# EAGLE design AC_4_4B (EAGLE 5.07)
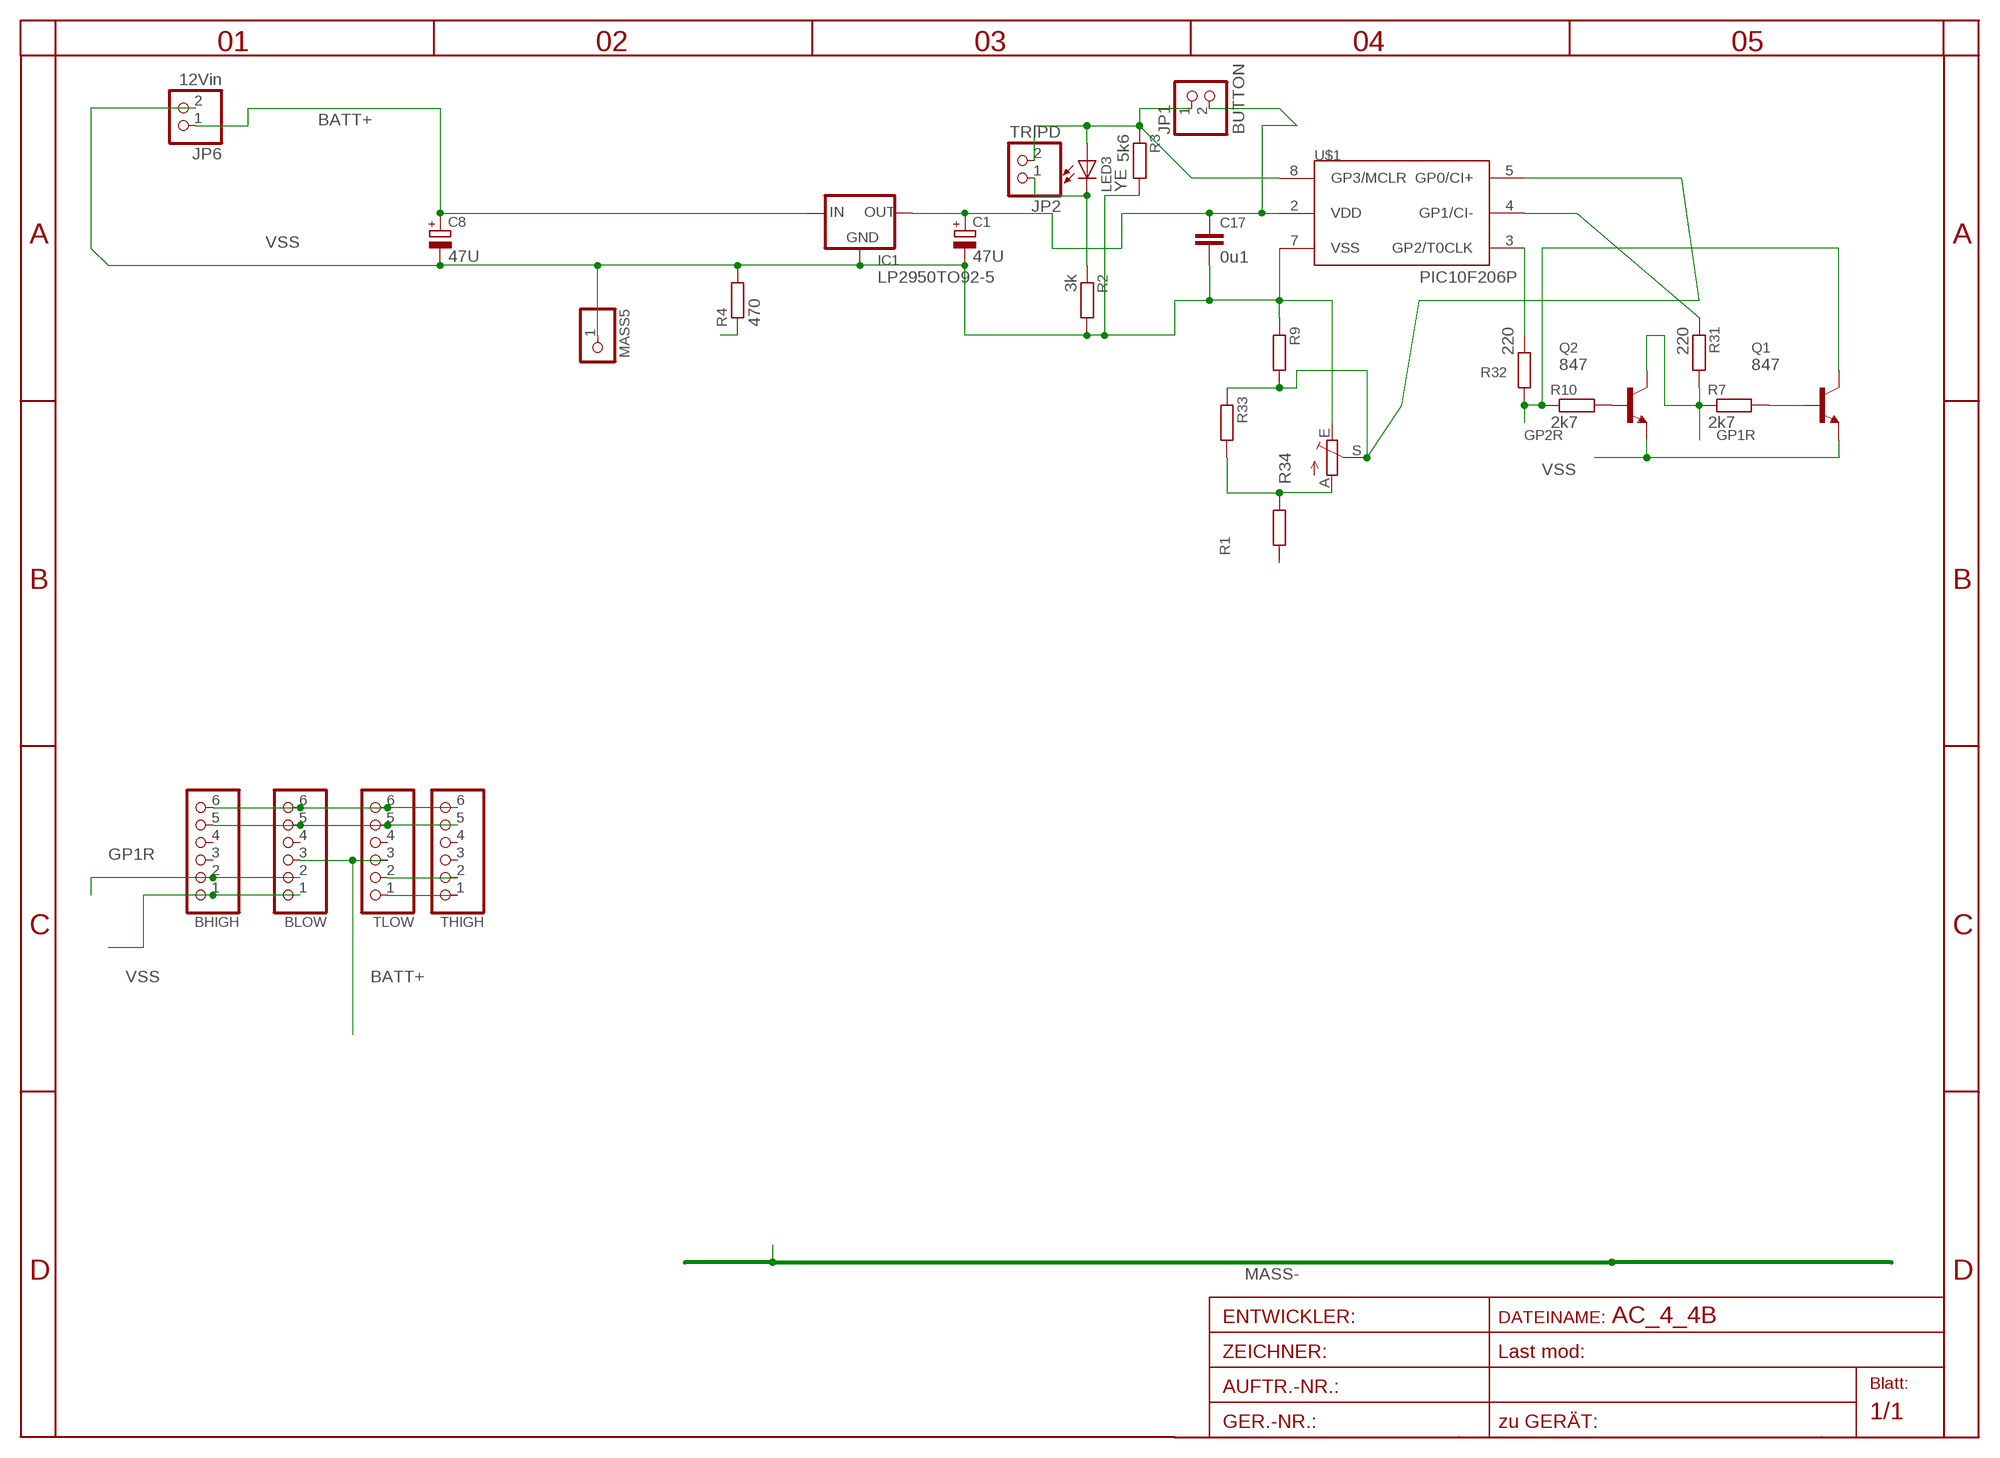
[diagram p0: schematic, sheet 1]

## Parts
BHIGH  PINHD-1X6  [1X06BOX]
BLOW  PINHD-1X6  [1X06BOX]
C1  47U  CPOL-EUE5-6  [E5-6]
C8  47U  CPOL-EUE5-5  [E5-5]
C17  0u1  C-EUC1206  [C1206]
IC1  LP2950TO92-5  [T092-5]
JP1  BUTTON  PINHD-1X2/90  [1X02/90]
JP2  TRIPD  PINHD-1X2/90  [1X02/90]
JP6  12Vin  PINHD-1X2STR  [1X02]
LED3  YE  LEDCHIPLED_1206  [CHIPLED_1206]
MASS5  PINHD-1X11MM6  [1X1MM8]
Q1  847  BC847ALT1SMD  [SOT23]
Q2  847  BC847ALT1SMD  [SOT23]
R1  R-EU_0207/35  [0207/35]
R2  3k  R-EU_R0805  [R0805]
R3  5k6  R-EU_R0805  [R0805]
R4  470  R-EU_0204/5  [0204/5]
R7  2k7  R-EU_R0805  [R0805]
R9  R-EU_R0805  [R0805]
R10  2k7  R-EU_R0805  [R0805]
R31  220  R-EU_R1206  [R1206]
R32  220  R-EU_R1206  [R1206]
R33  R-EU_R0805  [R0805]
R34  TRIM_EU-S64W  [S64W]
THIGH  PINHD-1X6  [1X06BOX]
TLOW  PINHD-1X6  [1X06BOX]
U$1  PIC10F206P  [DIL8]

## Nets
BATT+: BLOW.3 C8.+ IC1.3(IN) JP6.1 TLOW.3
GP1R: BHIGH.2 BLOW.2 Q2.3(C) R7.1 R31.2
GP2R: Q1.3(C) R10.1 R32.2 THIGH.2 TLOW.2
GP3: BHIGH.6 BLOW.6 JP1.1 JP2.2 LED3.A R3.1 THIGH.6 TLOW.6 U$1.8(GP3/MCLR)
N$1: R9.2 R33.1 R34.S U$1.5(GP0/CI+)
N$4: Q2.1(B) R10.2
N$7: Q1.1(B) R7.2
N$15: JP2.1 LED3.C R2.1
N$34: R4.1
N$39: R31.1 U$1.4(GP1/CI-)
N$42: R1.1 R33.2 R34.A
N$43: R32.1 U$1.3(GP2/T0CLK)
VDD: BHIGH.5 BLOW.5 C1.+ C17.1 IC1.1(OUT) JP1.2 THIGH.5 TLOW.5 U$1.2(VDD)
VSS: BHIGH.1 BLOW.1 C1.- C8.- C17.2 IC1.2(GND) JP6.2 MASS5.1 Q1.2(E) Q2.2(E) R2.2 R3.2 R4.2 R9.1 R34.E THIGH.1 TLOW.1 U$1.7(VSS)
Unconnected: BHIGH.3 BHIGH.4 BLOW.4 R1.2 THIGH.3 THIGH.4 TLOW.4

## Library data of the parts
BHIGH BLOW THIGH TLOW = pinhead:PINHD-1X6: PIN HEADER
C1 C8 = rcl-2:CPOL-EU: POLARIZED CAPACITOR, European symbol
C17 = rcl-2:C-EU: CAPACITOR, European symbol
IC1 = v-reg:LP2950?*: Source: http://cache.national.com/ds/LP/LP2950.pdf
JP1 JP2 JP6 = pinhead:PINHD-1X2: PIN HEADER
LED3 = led:LED: LED
MASS5 = pinhead:PINHD-1X1: PIN HEADER
Q1 Q2 = transistor-npn:BC847*: NPN Transistor
R1-R4 R7 R9 R10 R31-R33 = rcl-2:R-EU_: RESISTOR, European symbol
R34 = pot:TRIM_EU-: POTENTIOMETER
U$1 = microchip-5:PIC10F2*: uPC nW 0,25/0,5k Program Flash memory Comparator

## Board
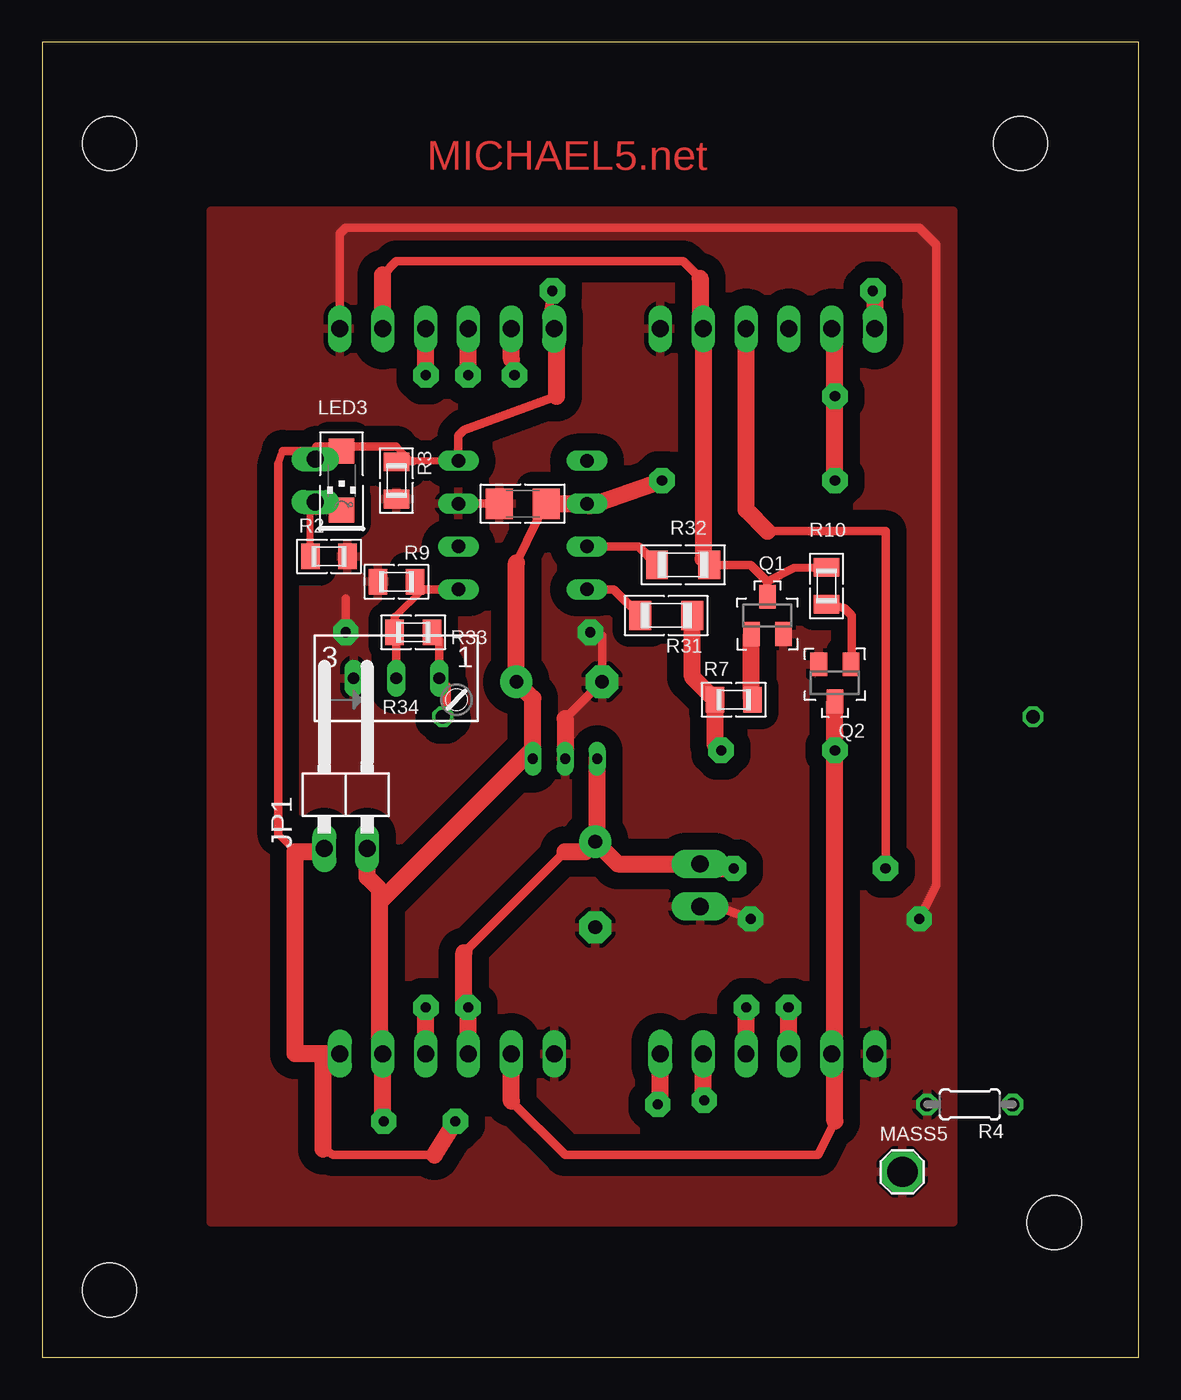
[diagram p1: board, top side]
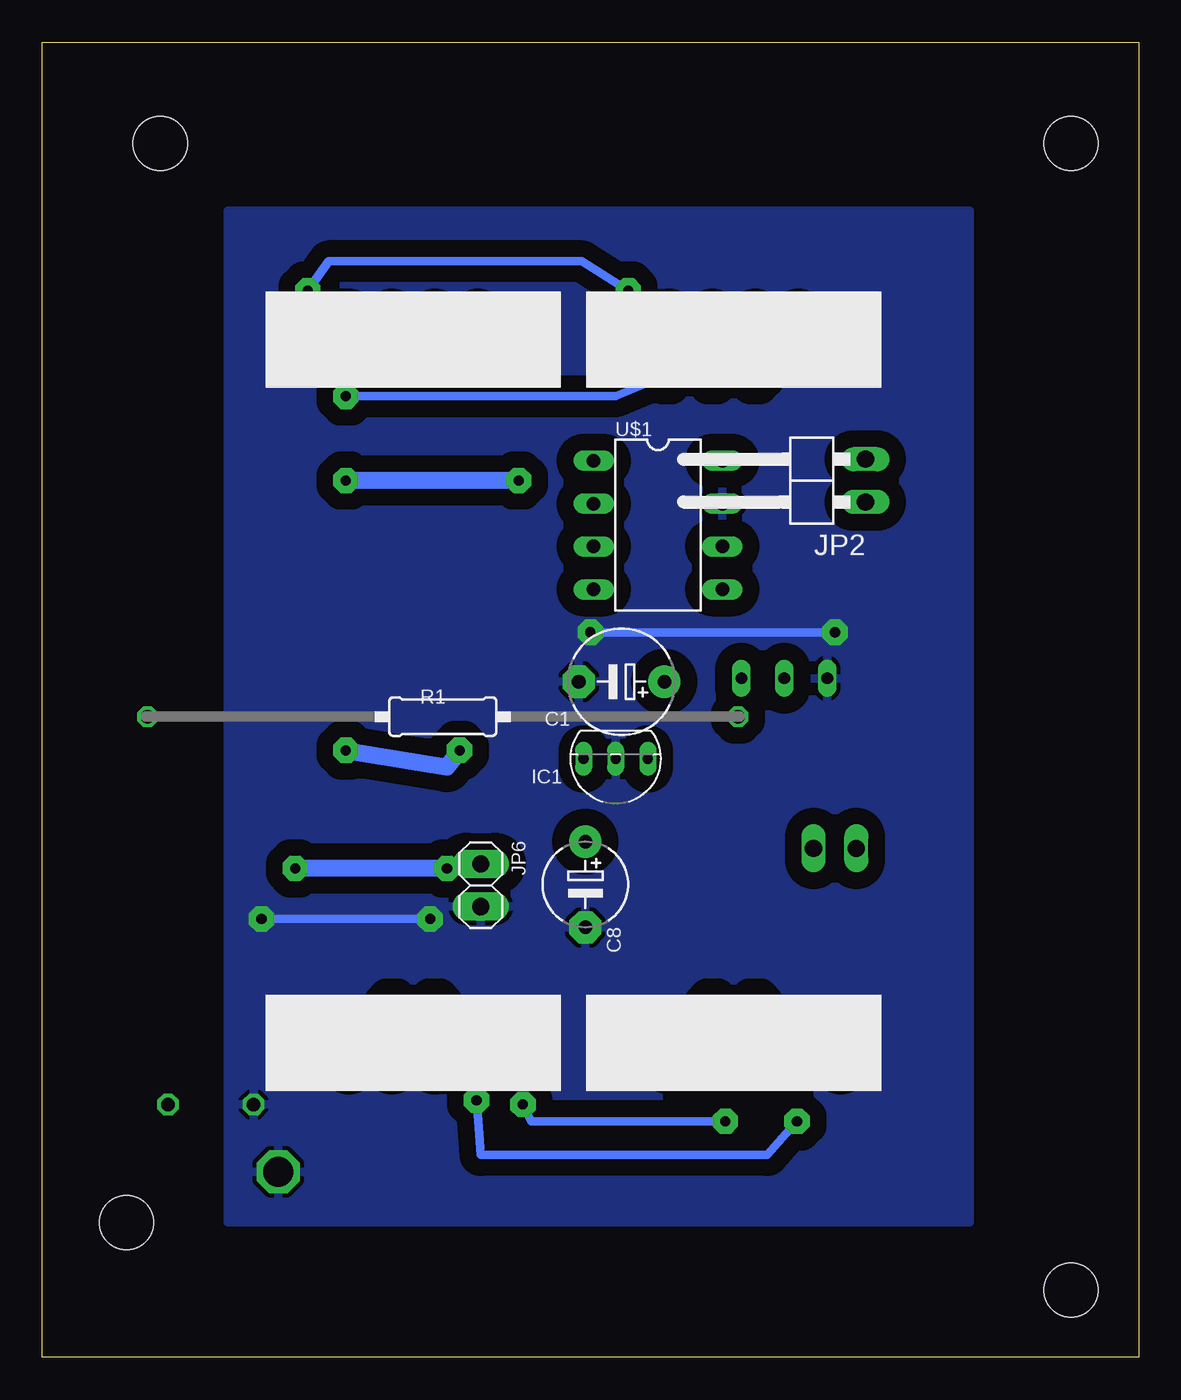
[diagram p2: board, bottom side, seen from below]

Size 65 x 78 mm. Coordinates in mm from the lower left corner, seen from the top.
Outline: 0,0 65,0 65,78 0,78 0,0
Copper layers (1*16): Top 0.035mm / dielectric 1.5mm / Bottom 0.035mm
Design rules "default *": minimum track width 12mil, minimum drill 24mil, track to track 8mil, track to pad 8mil, pad to pad 8mil, via to via 8mil, smd to smd 8mil, copper to edge 40mil, drill to drill 8mil, minimum pad ring 8mil, minimum via ring 8mil, stop-mask expansion 4mil, vias tented up to drill 0mil, thermal gap 10mil
Holes 3.2 mm at 4,72 4,4 58,72 60,8

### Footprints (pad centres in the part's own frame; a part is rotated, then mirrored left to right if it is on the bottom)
1X06BOX = drill 1 long: 1 -6.35,0; 2 -3.81,0; 3 -1.27,0; 4 1.27,0; 5 3.81,0 | drill 1.016 long: 6 6.35,0
E5-6 = drill 0.813 pad 1.905 round: + -2.54,0 | drill 0.813 pad 1.905 octagon: - 2.54,0
E5-5 = drill 0.813 pad 1.905 round: + -2.54,0 | drill 0.813 pad 1.905 octagon: - 2.54,0
C1206 = smd 1.6 x 1.8: 1 -1.4,0; 2 1.4,0
T092-5 = drill 0.6 pad 0.813 long: 1 -1.905,0; 2 0,0; 3 1.905,0
1X02/90 = drill 1.016 long: 1 -1.27,-3.81; 2 1.27,-3.81
1X02 = drill 1.016 pad 1.676 long: 1 -1.27,0; 2 1.27,0
CHIPLED_1206 = smd 1.5 x 1.5: A 0,-1.75; C 0,1.75
1X1MM8 = drill 1.8 pad 2.54 octagon: 1 0,0
SOT23 = smd 1 x 1.4: 1 -0.95,-1.1; 2 0.95,-1.1; 3 0,1.1
0207/35 = drill 0.813 octagon: 1 -17.5,0; 2 17.5,0
R0805 = smd 1.1 x 1.5: 1 -1.1,0; 2 1.1,0
0204/5 = drill 0.8 pad 1.27 octagon: 1 -2.54,0; 2 2.54,0
R1206 = smd 1.3 x 1.7: 1 -1.55,0; 2 1.55,0
S64W = drill 0.7 long: A 2.54,1.27; E -2.54,1.27; S 0,1.27
DIL8 = drill 0.8 long: 1 -3.81,-3.81; 2 -1.27,-3.81; 3 1.27,-3.81; 4 3.81,-3.81; 5 3.81,3.81; 6 1.27,3.81; 7 -1.27,3.81; 8 -3.81,3.81

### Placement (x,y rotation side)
BHIGH  43,18 0 bottom
BLOW  24,18 0 bottom
C1  30.65,40.07 180 bottom
C8  32.8,28.05 270 bottom
C17  28.49,50.63 180 top
IC1  31,35.5 180 bottom
JP1  18,34 0 top
JP2  20,52 90 bottom
JP6  39,28 270 bottom
LED3  17.75,52 180 top
MASS5  51,11 0 top
Q1  43,44 0 top
Q2  47,40 180 top
R1  41.25,38 180 bottom
R2  17,47.5 0 top
R3  21,52 270 top
R4  55,15 180 top
R7  41,39 0 top
R9  21,46 0 top
R10  46.5,45.75 270 top
R31  37,44 0 top
R32  38,47 0 top
R33  22,43 0 top
R34  21,39 0 top
THIGH  24,61 180 bottom
TLOW  43,61 180 bottom
U$1  28.49,49.36 270 bottom

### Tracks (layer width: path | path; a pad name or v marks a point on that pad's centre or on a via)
BATT+  (via drill 0.6 pad 1.5)
  Top 0.406: BLOW.3 25.27,20.73 25,21 | 32.21,30 C8.+
  Top 0.5: 25,24 31,30 | 43,49 50,49 v50,29
  Top 1: 25,21 25,24 | 31,30 32.21,30 | IC1.3 32.91,30.7 C8.+ 34.11,29.27 JP6.1 39.27,29 v41,29 | TLOW.3 41.73,50.27 43,49
  Bottom 1: v41,29 v50,29
GP1R  (via drill 0.6 pad 1.5)
  Top 0.5: 27.81,15.19 31,12 46,12 47,14 | 47,17.81 BHIGH.2
  Top 1: 47,14 47,17.81 | 27.81,15.19 BLOW.2 | R31.2 38.55,40.35 R7.1 39.9,36.35 v40.25,36 | Q2.3 47,37 v47,36 47,18.19 BHIGH.2
  Bottom 1: v40.25,36 41,35 v47,36
GP2R
  Top 0.5: R10.1 44.55,46.8 43,46 | 43,46 Q1.3 | 43,46 42,47 R32.2 39.19,47.36 | 20.19,64.19 21,65 38,65 39,64 | 39,61.19 TLOW.2
  Top 1: THIGH.2 20.19,64.19 | 39,64 39,61.19 | TLOW.2 39.19,47.36
GP3  (via drill 0.6 pad 1.5)
  Top 0.406: 22,53.17 21.83,53.17 21,54 | 22,53.17 U$1.8 | LED3.A 16.25,54 | 14,53 14.25,53.75 | 15,30 14,31 | JP2.2 16,53.27 16,53.75 | R3.1 22,53.1 22,53.17
  Top 0.5: 16.65,12.35 17.25,12 23.25,12 | 16.65,17.65 17,18 | v36.5,15 36.5,15.5 | U$1.8 24.68,54.68 25,55 30.5,57 | 30.5,60.35 THIGH.6 30,61.35 30,62 v30.25,63.25 | v49.25,63.25 49.35,62.65 | 16.25,54 21,54 | 14.25,53.75 16,53.75 LED3.A | 14,31 14,53
  Top 1: 23.25,12 v24.5,14 | 16.65,12.35 16.65,17.65 | 17,18 BLOW.6 15,18 15,30 16.54,30 JP1.1 | 30.5,57 30.5,60.35 | 49.35,62.65 TLOW.6 | BHIGH.6 36.65,15.15 v36.5,15
  Bottom 0.5: v24.5,14 36,14 v36.5,15 | v49.25,63.25 48,65 33,65 v30.25,63.25
N$1
  Top 0.406: 21,42.9 R33.1 | 20.9,43.9 22.55,45.55
  Top 0.5: U$1.5 22.55,45.55 R9.2 | R34.S 21,42.9 | R33.1 20.9,43.9
N$4
  Top 0.5: R10.2 47.55,44.45 48,44 48,41.15 Q2.1
N$5  (via drill 0.6 pad 1.5)
  Top 1: 44.25,18 v44.25,20.75
N$7
  Top 1: Q1.1 42.05,39.05 R7.2
N$8  (via drill 0.6 pad 1.5)
  other vias: 41.75,20.75
N$10  (via drill 0.6 pad 1.5)
  other vias: 22.75,20.75
N$15
  Top 0.406: R2.1 15.9,50.15 LED3.C 17.75,50.73 JP2.1
N$18  (via drill 0.6 pad 1.5)
  Top 1: 25.25,18 v25.25,20.75
N$29  (via drill 0.6 pad 1.5)
  Top 1: v25.25,58.25 25.25,61
N$30  (via drill 0.6 pad 1.5)
  Top 1: v22.75,58.25 22.75,61
N$31
  Top 1: 41.75,18 41.75,20.5
N$32
  Top 1: 22.75,18 22.75,20.5
N$39
  Top 0.5: U$1.4 33.9,45.55 R31.1
N$42
  Top 0.406: 24,39.81 R34.A | 23.54,42.56 R33.2
  Top 0.5: 24,39.81 24,38 24.17,37.83 R1.1 | R34.A 23.54,42.56
N$43
  Top 0.5: U$1.3 35.36,48.09 R32.1
VDD  (via drill 0.6 pad 1.5)
  Top 0.5: 28.11,47.11 30,51 30,50.52 C17.1 | v39.25,15.25 39.19,15.19 | 47,60.81 TLOW.5 | IC1.1 29.09,35.09 29,35 29,36 | BLOW.5 20,18.19 | v20.25,14 20.19,14.31 | v28,58.25 27.81,59.19
  Top 1: IC1.1 29.09,39.09 C1.+ 28.11,47.11 | C17.1 U$1.2 32.43,50.5 v36.75,52 | 20,27 29,36 | 20,27 20,27.75 19.27,28.48 JP1.2 | 39.19,15.19 BHIGH.5 | 47,60.81 v47,57 v47,52 | 20,18.19 20,27 | 20.19,14.31 BLOW.5 | 27.81,59.19 THIGH.5
  Bottom 0.5: v39.25,15.25 39,12 22,12 v20.25,14 | v47,52 39,52 | v28,58.25 31,57 v47,57
  Bottom 1: v36.75,52 v47,52
VSS  (via drill 0.6 pad 1.5)
  Top 0.5: 24.68,51 U$1.7 C17.2 | 31,37.88 C1.- 33.19,42.81 v32.5,43 | v18,43 18,45 | THIGH.1 17.65,66.65 18,67 52,67 53,66 53,28 v52,26 | v42,26 39.27,27 JP6.2
  Top 1: 31,37.88 IC1.2
  Bottom 0.5: v18,43 v32.5,43 | v42,26 v52,26
  pour Top (isolate 1): 10,68 54,68 54,8 10,8
  pour Bottom (isolate 1): 10,68 54,68 54,8 10,8

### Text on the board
Top: MICHAEL5.net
